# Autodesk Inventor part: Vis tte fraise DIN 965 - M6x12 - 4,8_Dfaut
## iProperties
Created: 2007-07
Part Number: Vis tte fraise DIN 965 - M6x12 - 4,8_Dfaut
Document SubType Name: Modeling
Designer: EF
Density: 1 g/cm^3
Author: EF
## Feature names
1. Base1
